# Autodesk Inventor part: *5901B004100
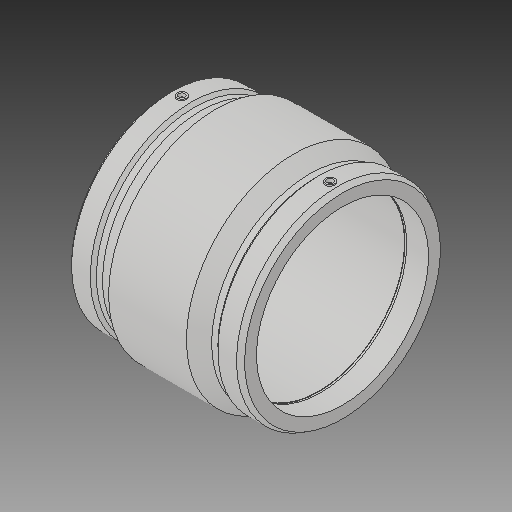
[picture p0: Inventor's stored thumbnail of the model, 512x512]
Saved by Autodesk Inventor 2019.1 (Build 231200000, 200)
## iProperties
Created: 2017-06
Part Number: *5901B004100
Material: Generic
Description: PLASSON IPS COUPLER 10''
Document SubType Name: Modeling
Designer: KIM
Mass: 8622.19 g
Surface Area: 6772.47 cm^2
Volume: 8622.19 cm^3
Density: 1 g/cm^3
Appearance: Default
Author: KIM
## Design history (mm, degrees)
derived "5901B.ipt"
feature "Solid1::5901B.ipt"
tag "TaggingFeature1"
body "Solid1"
other parameters: "d0" = 274.32, "d1" = 272.7, "d2" = 340.36, "d3" = 135.382, "d4" = 68.58, "d5" = 306.324, "d6" = 218.16, "d7" = 272.7, "d8" = 168 deg, "d10" = 54.1528, "d11" = 18.05093, "d13" = 274.32, "d14" = 17.6296, "d18" = 272.7, "d19" = 3.52592, "d20" = 168 deg, "d22" = 319.9384, "d23" = 340.36, "d24" = 310.34025, "d25" = 135 deg, "d26" = 123.444, "d27" = 135 deg, "d29" = 161.798, "d30" = 15, "d31" = 96.012, "d34" = 5 deg, "d35" = 15, "d39" = 5 deg, "d41" = 4, "d42" = 14, "d43" = 0, "d45" = 4, "d46" = 14, "d47" = 0, "d48" = 3, "d49" = 0, "d50" = 3, "d51" = 0, "d52" = 39.26078, "d53" = 9.81519, "d55" = 135.382, "d_" = 272.7, "L_" = 274.32, "L_1" = 135.382, "D_" = 340.36, "A_" = 161.798, "d_2" = 12, "B_" = 161.798
